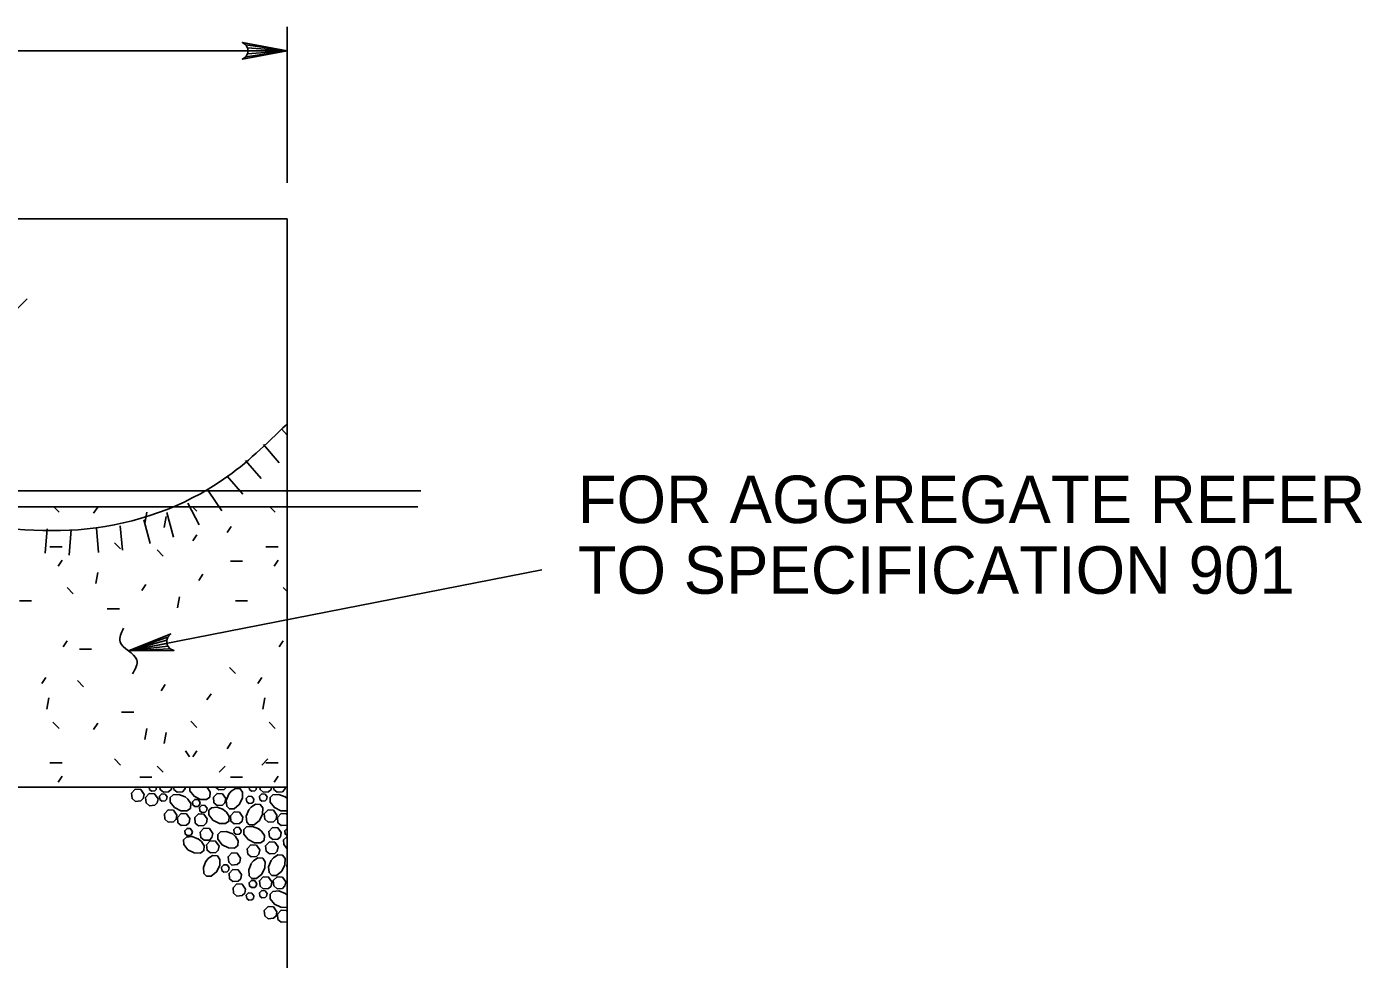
# Model space of a CAD drawing. Extents: x 1.32 to 7.47, y -3.56 to 5.14.
# Drawn here: x 4.69 to 6.376, y 3.906 to 5.083 of the extents above; entities that cross this region are included whole.
import ezdxf

# ---------------------------------------------------------------- set-up
doc = ezdxf.new("R2010")
doc.units = 0
for name, color, linetype in [('DETL-DIMS', 7, 'Continuous'), ('DETL-LINE', 7, 'Continuous'), ('DETL-NOTE', 7, 'Continuous'), ('DETL-PATT', 7, 'Continuous')]:
    doc.layers.add(name, color=color, linetype=linetype)

msp = doc.modelspace()

# ---------------------------------------------------------------- linework, layer by layer
at = {"layer": 'DETL-DIMS'}
for p, q in [((5.0188, 5.0832), (5.0188, 4.8863)), ((5.0188, 5.0529), (2.5946, 5.0529)), ((5.3401, 4.3976), (4.8185, 4.2955))]:
    msp.add_line(p, q, dxfattribs=at)
for points in [[(5.0188, 5.0529), (4.9623, 5.0423), (4.9667, 5.0453), (4.9689, 5.0491), (4.9696, 5.0529), (4.9689, 5.0567), (4.9667, 5.0605), (4.9623, 5.0635), (5.0188, 5.0529), (4.9667, 5.0605), (4.9689, 5.0567), (5.0188, 5.0529), (4.9696, 5.0529), (4.9689, 5.0491), (5.0188, 5.0529), (4.9667, 5.0453)], [(4.8185, 4.2955), (4.8719, 4.3168), (4.8682, 4.313), (4.8667, 4.3088), (4.8668, 4.305), (4.8682, 4.3014), (4.8711, 4.2981), (4.8759, 4.296), (4.8185, 4.2955), (4.8711, 4.2981), (4.8682, 4.3014), (4.8185, 4.2955), (4.8668, 4.305), (4.8667, 4.3088), (4.8185, 4.2955), (4.8682, 4.313)]]:
    msp.add_lwpolyline(points, dxfattribs=at)
msp.add_spline([(4.8235, 4.2664), (4.829, 4.2842), (4.8078, 4.307), (4.8124, 4.3243)], degree=3, dxfattribs=at)
at = {"layer": 'DETL-LINE'}
for p, q in [((5.0188, 4.8408), (2.5946, 4.8408)), ((5.0188, 3.4469), (5.0188, 4.8408)), ((5.1877, 4.4974), (2.4245, 4.4974)), ((5.1837, 4.4772), (2.4245, 4.4772)), ((2.5946, 4.1236), (5.0188, 4.1236))]:
    msp.add_line(p, q, dxfattribs=at)
msp.add_spline([(4.3029, 4.2955), (4.3159, 4.3122), (4.3511, 4.3906), (4.4255, 4.4455), (4.5861, 4.4572), (4.7663, 4.4494), (4.9386, 4.5121), (5.0182, 4.5814)], degree=3, dxfattribs=at)
at = {"layer": 'DETL-PATT'}
for p, q in [((4.6262, 4.6756), (4.6905, 4.7399)), ((5.0117, 4.5757), (5.0188, 4.5676)), ((4.9889, 4.5558), (5.0087, 4.533)), ((4.966, 4.5359), (4.9859, 4.5131)), ((4.9431, 4.5161), (4.963, 4.4932)), ((4.9193, 4.4972), (4.9364, 4.4721)), ((4.7241, 4.4772), (4.7308, 4.4704)), ((4.7745, 4.4691), (4.7797, 4.4768)), ((4.8418, 4.4704), (4.8392, 4.4563)), ((4.8667, 4.4702), (4.8751, 4.439)), ((4.8936, 4.4821), (4.9076, 4.4545)), ((4.8992, 4.4772), (4.9047, 4.4717)), ((4.9968, 4.4772), (5.0036, 4.4704)), ((4.8081, 4.4531), (4.8109, 4.4226)), ((4.8378, 4.4609), (4.8458, 4.4311)), ((4.8662, 4.4652), (4.8636, 4.4511)), ((4.9432, 4.4447), (4.9483, 4.4524)), ((4.7157, 4.4494), (4.7132, 4.4188)), ((4.746, 4.4487), (4.7434, 4.4163)), ((4.7779, 4.4503), (4.7807, 4.4198)), ((4.8996, 4.4344), (4.9047, 4.4421)), ((4.7193, 4.4267), (4.7347, 4.4267)), ((4.8007, 4.4319), (4.8084, 4.4242)), ((4.8546, 4.4229), (4.8623, 4.4152)), ((4.992, 4.4267), (5.0074, 4.4267)), ((4.7296, 4.4023), (4.7347, 4.41)), ((4.9471, 4.4087), (4.9625, 4.4087)), ((5.0023, 4.4023), (5.0074, 4.41)), ((4.7797, 4.3946), (4.7771, 4.3805)), ((4.9073, 4.3843), (4.9124, 4.3921)), ((4.7411, 4.3753), (4.7488, 4.3676)), ((4.8353, 4.3715), (4.8405, 4.3792)), ((5.0139, 4.3753), (5.0188, 4.3704)), ((4.6808, 4.3587), (4.6962, 4.3587)), ((4.8828, 4.3638), (4.8803, 4.3497)), ((4.9535, 4.3587), (4.9689, 4.3587)), ((4.7917, 4.3484), (4.8071, 4.3484)), ((4.736, 4.3004), (4.7411, 4.3081)), ((5.0087, 4.3004), (5.0138, 4.3081)), ((4.7565, 4.2978), (4.7719, 4.2978)), ((4.9458, 4.2747), (4.9535, 4.267)), ((4.709, 4.2542), (4.7142, 4.2619)), ((4.754, 4.258), (4.7617, 4.2503)), ((4.8597, 4.2452), (4.8649, 4.2529)), ((4.9817, 4.2542), (4.9869, 4.2619)), ((4.718, 4.2362), (4.7154, 4.2221)), ((4.9175, 4.2336), (4.9227, 4.2413)), ((4.9907, 4.2362), (4.9882, 4.2221)), ((4.8097, 4.2182), (4.8251, 4.2182)), ((4.7231, 4.2054), (4.7308, 4.1977)), ((4.7745, 4.1964), (4.7797, 4.2041)), ((4.897, 4.2066), (4.9047, 4.1989)), ((4.9959, 4.2054), (5.0036, 4.1977)), ((4.8418, 4.1977), (4.8392, 4.1835)), ((4.8662, 4.1925), (4.8636, 4.1784)), ((4.8956, 4.1617), (4.8905, 4.1694)), ((4.8996, 4.1617), (4.9047, 4.1694)), ((4.9432, 4.172), (4.9483, 4.1797)), ((4.7193, 4.154), (4.7347, 4.154)), ((4.8007, 4.1591), (4.8084, 4.1514)), ((4.8546, 4.1501), (4.8623, 4.1424)), ((4.9406, 4.1501), (4.9329, 4.1424)), ((4.9945, 4.1591), (4.9868, 4.1514)), ((4.992, 4.154), (5.0074, 4.154)), ((4.7296, 4.1296), (4.7347, 4.1373)), ((4.8481, 4.136), (4.8327, 4.136)), ((4.9471, 4.136), (4.9625, 4.136)), ((5.0023, 4.1296), (5.0074, 4.1373)), ((5.0188, 4.109), (5.0158, 4.1115)), ((5.0188, 3.9871), (5.0158, 3.9895))]:
    msp.add_line(p, q, dxfattribs=at)
for points in [[(4.8381, 4.1144), (4.8339, 4.1204), (4.8271, 4.1208), (4.8224, 4.1159), (4.8231, 4.1091), (4.8273, 4.1056), (4.8339, 4.1061), (4.8371, 4.1092), (4.8381, 4.1144)], [(4.8558, 4.1089), (4.8515, 4.1149), (4.8448, 4.1153), (4.84, 4.1104), (4.8407, 4.1036), (4.8449, 4.1001), (4.8516, 4.1006), (4.8548, 4.1036), (4.8558, 4.1089)], [(4.8448, 4.1236), (4.845, 4.1207), (4.8476, 4.1186), (4.8516, 4.1189), (4.8535, 4.1207), (4.854, 4.1236)], [(4.8672, 4.1111), (4.8647, 4.1148), (4.8606, 4.115), (4.8578, 4.1121), (4.8582, 4.108), (4.8607, 4.1059), (4.8647, 4.1062), (4.8666, 4.108), (4.8672, 4.1111)], [(4.858, 4.1236), (4.8583, 4.1204), (4.8625, 4.117), (4.8692, 4.1175), (4.8724, 4.1205), (4.873, 4.1236)], [(4.8899, 4.1113), (4.8819, 4.1144), (4.8747, 4.1138), (4.8712, 4.1105), (4.8713, 4.1046), (4.8766, 4.0978), (4.8847, 4.0938), (4.8923, 4.0937), (4.8967, 4.0967), (4.8971, 4.1028), (4.8936, 4.1083), (4.8896, 4.1115)], [(4.8755, 4.1236), (4.8758, 4.1207), (4.88, 4.1172), (4.8867, 4.1177), (4.8898, 4.1208), (4.8904, 4.1236)], [(4.8958, 4.1236), (4.8959, 4.1188), (4.9012, 4.112), (4.9093, 4.108), (4.917, 4.1078), (4.9213, 4.1109), (4.9217, 4.117), (4.9182, 4.1225), (4.9167, 4.1236)], [(4.9414, 4.1091), (4.9371, 4.1152), (4.9304, 4.1156), (4.9256, 4.1107), (4.9263, 4.1038), (4.9305, 4.1004), (4.9372, 4.1008), (4.9403, 4.1039), (4.9414, 4.1091)], [(4.9283, 4.1236), (4.9324, 4.1202), (4.9391, 4.1207), (4.9421, 4.1236)], [(4.945, 4.1147), (4.9418, 4.1068), (4.9425, 4.0995), (4.9458, 4.096), (4.9517, 4.0961), (4.9584, 4.1014), (4.9625, 4.1095), (4.9626, 4.1172), (4.9595, 4.1215), (4.9534, 4.1219), (4.948, 4.1184), (4.9448, 4.1144)], [(4.9709, 4.1236), (4.9712, 4.1207), (4.9737, 4.1186), (4.9778, 4.1189), (4.9797, 4.1207), (4.9802, 4.1236)], [(4.9934, 4.1111), (4.9909, 4.1148), (4.9868, 4.115), (4.984, 4.1121), (4.9844, 4.108), (4.9869, 4.1059), (4.9909, 4.1062), (4.9928, 4.108), (4.9934, 4.1111)], [(4.9842, 4.1236), (4.9845, 4.1204), (4.9887, 4.117), (4.9954, 4.1175), (4.9985, 4.1205), (4.9992, 4.1236)], [(5.0161, 4.1113), (5.0081, 4.1144), (5.0008, 4.1138), (4.9974, 4.1105), (4.9975, 4.1046), (5.0027, 4.0978), (5.0109, 4.0938), (5.0185, 4.0937), (5.0188, 4.0938)], [(5.0017, 4.1236), (5.002, 4.1207), (5.0062, 4.1172), (5.0129, 4.1177), (5.016, 4.1208), (5.0166, 4.1236)], [(4.9088, 4.1042), (4.9063, 4.1078), (4.9022, 4.108), (4.8994, 4.1051), (4.8998, 4.101), (4.9023, 4.0989), (4.9063, 4.0992), (4.9082, 4.101), (4.9088, 4.1042)], [(4.9176, 4.0968), (4.915, 4.1004), (4.9109, 4.1007), (4.9081, 4.0977), (4.9085, 4.0936), (4.911, 4.0915), (4.9151, 4.0918), (4.9169, 4.0937), (4.9176, 4.0968)], [(4.9384, 4.0951), (4.9305, 4.0982), (4.9232, 4.0976), (4.9197, 4.0943), (4.9198, 4.0884), (4.9251, 4.0817), (4.9332, 4.0776), (4.9409, 4.0775), (4.9452, 4.0805), (4.9456, 4.0866), (4.9421, 4.0921), (4.9381, 4.0953)], [(4.9703, 4.0947), (4.9671, 4.0868), (4.9677, 4.0795), (4.971, 4.076), (4.977, 4.0761), (4.9837, 4.0814), (4.9878, 4.0895), (4.9879, 4.0972), (4.9848, 4.1015), (4.9787, 4.1019), (4.9733, 4.0984), (4.9701, 4.0944)], [(4.9767, 4.1082), (4.9741, 4.1118), (4.9701, 4.112), (4.9672, 4.1091), (4.9677, 4.105), (4.9702, 4.1029), (4.9742, 4.1032), (4.9761, 4.105), (4.9767, 4.1082)], [(4.8795, 4.0882), (4.8752, 4.0943), (4.8685, 4.0947), (4.8638, 4.0898), (4.8644, 4.0829), (4.8686, 4.0794), (4.8753, 4.0799), (4.8785, 4.083), (4.8795, 4.0882)], [(4.8959, 4.0838), (4.8917, 4.0898), (4.8849, 4.0902), (4.8802, 4.0853), (4.8809, 4.0785), (4.8851, 4.075), (4.8918, 4.0755), (4.8949, 4.0786), (4.8959, 4.0838)], [(4.9178, 4.0836), (4.9136, 4.0896), (4.9068, 4.09), (4.9021, 4.0851), (4.9028, 4.0782), (4.907, 4.0748), (4.9137, 4.0753), (4.9168, 4.0783), (4.9178, 4.0835)], [(4.9629, 4.0858), (4.9586, 4.0918), (4.9519, 4.0922), (4.9472, 4.0873), (4.9478, 4.0805), (4.952, 4.077), (4.9587, 4.0775), (4.9619, 4.0805), (4.9629, 4.0858)], [(5.0057, 4.0882), (5.0014, 4.0943), (4.9947, 4.0947), (4.9899, 4.0898), (4.9906, 4.0829), (4.9948, 4.0794), (5.0015, 4.0799), (5.0047, 4.083), (5.0057, 4.0882)], [(5.0188, 4.0885), (5.0179, 4.0898), (5.0111, 4.0902), (5.0064, 4.0853), (5.0071, 4.0785), (5.0113, 4.075), (5.018, 4.0755), (5.0188, 4.0763)], [(4.8991, 4.0676), (4.8965, 4.0712), (4.8924, 4.0715), (4.8896, 4.0685), (4.89, 4.0644), (4.8925, 4.0624), (4.8966, 4.0626), (4.8984, 4.0645), (4.8991, 4.0676)], [(4.9248, 4.0651), (4.9206, 4.0712), (4.9138, 4.0716), (4.9091, 4.0667), (4.9098, 4.0598), (4.9139, 4.0564), (4.9206, 4.0568), (4.9238, 4.0599), (4.9248, 4.0651)], [(4.95, 4.0644), (4.942, 4.0675), (4.9347, 4.0669), (4.9313, 4.0636), (4.9314, 4.0577), (4.9366, 4.0509), (4.9448, 4.0469), (4.9524, 4.0467), (4.9567, 4.0498), (4.9571, 4.0559), (4.9536, 4.0614), (4.9496, 4.0646)], [(4.9609, 4.069), (4.9584, 4.0726), (4.9543, 4.0729), (4.9515, 4.0699), (4.9519, 4.0658), (4.9544, 4.0637), (4.9584, 4.064), (4.9603, 4.0659), (4.9609, 4.069)], [(4.9829, 4.0709), (4.9749, 4.074), (4.9676, 4.0734), (4.9642, 4.0701), (4.9643, 4.0642), (4.9695, 4.0575), (4.9777, 4.0534), (4.9853, 4.0533), (4.9896, 4.0563), (4.99, 4.0624), (4.9865, 4.0679), (4.9825, 4.0711)], [(5.0113, 4.0661), (5.0071, 4.0721), (5.0003, 4.0725), (4.9956, 4.0676), (4.9963, 4.0608), (5.0005, 4.0573), (5.0072, 4.0578), (5.0103, 4.0608), (5.0113, 4.0661)], [(5.0188, 4.0715), (5.0186, 4.0715), (5.0158, 4.0685), (5.0162, 4.0644), (5.0187, 4.0624), (5.0188, 4.0624)], [(4.9068, 4.058), (4.8989, 4.0611), (4.8916, 4.0605), (4.8881, 4.0572), (4.8882, 4.0513), (4.8935, 4.0445), (4.9016, 4.0405), (4.9093, 4.0403), (4.9136, 4.0434), (4.914, 4.0495), (4.9105, 4.055), (4.9065, 4.0582)], [(4.9328, 4.0492), (4.9285, 4.0552), (4.9218, 4.0556), (4.9171, 4.0507), (4.9177, 4.0439), (4.9219, 4.0404), (4.9286, 4.0409), (4.9318, 4.0439), (4.9328, 4.0492)], [(4.9841, 4.0443), (4.9799, 4.0503), (4.9731, 4.0507), (4.9684, 4.0458), (4.9691, 4.039), (4.9733, 4.0355), (4.98, 4.036), (4.9831, 4.039), (4.9841, 4.0443)], [(5.0073, 4.048), (5.0031, 4.054), (4.9963, 4.0544), (4.9916, 4.0495), (4.9923, 4.0427), (4.9965, 4.0392), (5.0032, 4.0397), (5.0063, 4.0427), (5.0073, 4.048)], [(5.0188, 4.0606), (5.0178, 4.0605), (5.0143, 4.0572), (5.0144, 4.0513), (5.0188, 4.0456)], [(4.9163, 4.0299), (4.9131, 4.022), (4.9137, 4.0147), (4.917, 4.0112), (4.9229, 4.0113), (4.9297, 4.0166), (4.9337, 4.0247), (4.9339, 4.0324), (4.9308, 4.0367), (4.9247, 4.0371), (4.9192, 4.0336), (4.916, 4.0296)], [(4.96, 4.034), (4.9558, 4.0401), (4.949, 4.0404), (4.9443, 4.0356), (4.945, 4.0287), (4.9491, 4.0252), (4.9558, 4.0257), (4.959, 4.0288), (4.96, 4.034)], [(4.9733, 4.0269), (4.9702, 4.019), (4.9708, 4.0117), (4.9741, 4.0082), (4.98, 4.0083), (4.9868, 4.0136), (4.9908, 4.0217), (4.991, 4.0294), (4.9879, 4.0337), (4.9818, 4.0341), (4.9763, 4.0306), (4.9731, 4.0266)], [(4.9985, 4.0308), (4.9954, 4.0228), (4.996, 4.0156), (4.9993, 4.0121), (5.0052, 4.0122), (5.0119, 4.0175), (5.016, 4.0256), (5.0161, 4.0333), (5.0131, 4.0376), (5.007, 4.038), (5.0015, 4.0345), (4.9983, 4.0305)], [(4.9454, 4.0217), (4.9429, 4.0253), (4.9388, 4.0255), (4.936, 4.0226), (4.9364, 4.0185), (4.9389, 4.0164), (4.9429, 4.0167), (4.9448, 4.0185), (4.9454, 4.0217)], [(4.9612, 4.0131), (4.957, 4.0191), (4.9502, 4.0195), (4.9455, 4.0146), (4.9461, 4.0078), (4.9503, 4.0043), (4.957, 4.0048), (4.9602, 4.0078), (4.9612, 4.0131)], [(5.0188, 4.0258), (5.0183, 4.0253), (5.0188, 4.02)], [(4.9662, 3.9949), (4.962, 4.0009), (4.9552, 4.0013), (4.9505, 3.9964), (4.9512, 3.9896), (4.9554, 3.9861), (4.9621, 3.9866), (4.9652, 3.9896), (4.9662, 3.9949)], [(4.9803, 4.002), (4.9777, 4.0056), (4.9736, 4.0058), (4.9708, 4.0029), (4.9712, 3.9988), (4.9737, 3.9967), (4.9778, 3.997), (4.9797, 3.9988), (4.9803, 4.0019)], [(4.9996, 4.0038), (4.9953, 4.0099), (4.9886, 4.0102), (4.9838, 4.0054), (4.9845, 3.9985), (4.9887, 3.995), (4.9954, 3.9955), (4.9985, 3.9986), (4.9996, 4.0038)], [(5.017, 4.0041), (5.0128, 4.0101), (5.006, 4.0105), (5.0013, 4.0056), (5.002, 3.9988), (5.0062, 3.9953), (5.0129, 3.9958), (5.016, 3.9988), (5.017, 4.0041)], [(4.9767, 3.9862), (4.9741, 3.9898), (4.9701, 3.9901), (4.9672, 3.9872), (4.9677, 3.983), (4.9702, 3.981), (4.9742, 3.9812), (4.9761, 3.9831), (4.9767, 3.9862)], [(4.9934, 3.9892), (4.9909, 3.9928), (4.9868, 3.9931), (4.984, 3.9901), (4.9844, 3.986), (4.9869, 3.9839), (4.9909, 3.9842), (4.9928, 3.9861), (4.9934, 3.9892)], [(5.0161, 3.9893), (5.0081, 3.9925), (5.0008, 3.9919), (4.9974, 3.9886), (4.9975, 3.9826), (5.0027, 3.9759), (5.0109, 3.9719), (5.0185, 3.9717), (5.0188, 3.9719)], [(5.0057, 3.9663), (5.0014, 3.9723), (4.9947, 3.9727), (4.9899, 3.9678), (4.9906, 3.961), (4.9948, 3.9575), (5.0015, 3.958), (5.0047, 3.961), (5.0057, 3.9663)], [(5.0188, 3.9666), (5.0179, 3.9679), (5.0111, 3.9683), (5.0064, 3.9634), (5.0071, 3.9566), (5.0113, 3.9531), (5.018, 3.9536), (5.0188, 3.9544)]]:
    msp.add_lwpolyline(points, dxfattribs=at)

# ---------------------------------------------------------------- texts
at = {"layer": 'DETL-NOTE'}
for s, p in [('FOR AGGREGATE REFER', (5.3856, 4.4567)), ('TO SPECIFICATION 901', (5.3856, 4.3676))]:
    msp.add_text(s, height=0.06, dxfattribs=at).set_placement(p)

doc.saveas('drawing.dxf')
